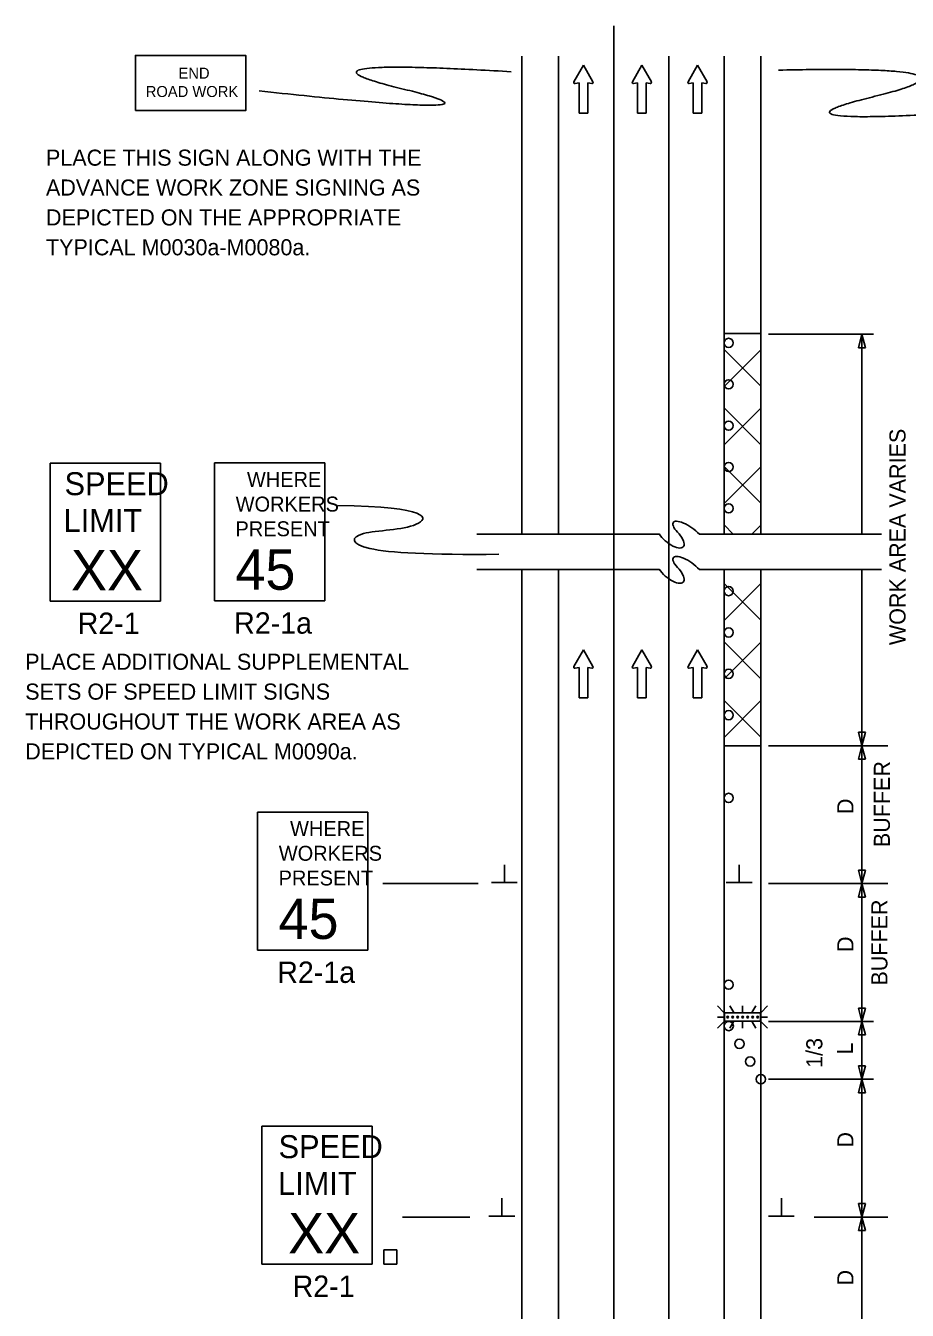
# Model space of a CAD drawing. Extents: x 16730 to 18471, y 7027 to 8225.
# Drawn here: x 16730 to 17113, y 7666 to 8225 of the extents above; entities that cross this region are included whole.
import ezdxf

# ---------------------------------------------------------------- set-up
doc = ezdxf.new("R2010")
doc.units = 0
for name, color, linetype in [('ALI_LEGAL_EX', 7, 'Continuous'), ('MT_SCRATCH_LEVEL_A', 7, 'Continuous'), ('MT_SCRATCH_LEVEL_E', 7, 'Continuous'), ('PAVT_EDGE_EX', 7, 'Continuous'), ('TRAFFIC_SIGNS_PR', 7, 'Continuous'), ('TYPICAL_EX', 7, 'Continuous'), ('TYPICAL_TEXT_DIMEN_PR', 7, 'Continuous')]:
    doc.layers.add(name, color=color, linetype=linetype)

msp = doc.modelspace()

# ---------------------------------------------------------------- linework, layer by layer
at = {"layer": 'ALI_LEGAL_EX'}
for points in [[(16985.65, 8225.29), (16985.65, 8200.29)], [(16985.65, 8216), (16985.65, 8191)], [(16985.65, 8211.96), (16985.65, 8200.29)], [(17009.65, 8211.96), (17009.65, 8200.29)], [(16985.65, 8125.29), (16985.65, 8100.29)], [(16985.65, 8125.29), (16985.65, 8100.29)], [(17009.65, 8125.29), (17009.65, 8100.29)], [(16985.65, 8025.29), (16985.65, 8004.01)], [(17009.65, 8025.29), (17009.65, 8000.29)], [(16985.65, 7961.57), (16985.65, 7936.57)], [(16985.65, 7925.29), (16985.65, 7900.29)], [(17009.65, 7925.29), (17009.65, 7900.29)], [(16985.65, 7825.29), (16985.65, 7800.29)], [(17009.65, 7825.29), (17009.65, 7800.29)], [(16985.65, 7725.29), (16985.65, 7700.29)], [(17009.65, 7725.29), (17009.65, 7700.29)]]:
    msp.add_lwpolyline(points, dxfattribs=at)
at = {"layer": 'MT_SCRATCH_LEVEL_A'}
for p, q in [((17049.65, 8068.41), (17033.65, 8084.41)), ((17033.65, 8068.3), (17049.65, 8084.3)), ((17049.65, 8042.96), (17033.65, 8058.96)), ((17033.65, 8042.85), (17049.65, 8058.85)), ((17049.65, 8017.5), (17033.65, 8033.5)), ((17033.65, 8017.39), (17049.65, 8033.39)), ((17037.68, 8004.02), (17033.65, 8008.05)), ((17045.64, 8003.92), (17049.65, 8007.94)), ((17049.65, 7966.59), (17033.65, 7982.59)), ((17033.65, 7966.48), (17049.65, 7982.48)), ((17049.65, 7941.13), (17033.65, 7957.13)), ((17033.65, 7941.02), (17049.65, 7957.02)), ((17049.65, 7915.68), (17033.65, 7931.68)), ((17033.65, 7915.57), (17049.65, 7931.57))]:
    msp.add_line(p, q, dxfattribs=at)
at = {"layer": 'MT_SCRATCH_LEVEL_E'}
for p, q in [((16972.46, 8208.07), (16968.34, 8200.83)), ((16972.46, 8208.07), (16968.34, 8200.83)), ((16976.6, 8200.83), (16972.46, 8208.07)), ((16976.6, 8200.83), (16972.46, 8208.07)), ((16997.88, 8208.07), (16993.77, 8200.83)), ((16997.88, 8208.07), (16993.77, 8200.83)), ((17002.03, 8200.83), (16997.88, 8208.07)), ((17002.03, 8200.83), (16997.88, 8208.07)), ((17022.09, 8208.07), (17017.98, 8200.83)), ((17022.09, 8208.07), (17017.98, 8200.83)), ((17026.24, 8200.83), (17022.09, 8208.07)), ((17026.24, 8200.83), (17022.09, 8208.07)), ((16968.83, 8200.14), (16970.6, 8200.46)), ((16968.83, 8200.14), (16970.6, 8200.46)), ((16970.6, 8200.46), (16970.6, 8187.2)), ((16970.6, 8200.46), (16970.6, 8187.2)), ((16974.35, 8187.2), (16974.35, 8200.46)), ((16974.35, 8200.46), (16976.12, 8200.14)), ((16974.35, 8187.2), (16974.35, 8200.46)), ((16974.35, 8200.46), (16976.12, 8200.14)), ((16994.25, 8200.14), (16996.03, 8200.46)), ((16994.25, 8200.14), (16996.03, 8200.46)), ((16996.03, 8200.46), (16996.03, 8187.2)), ((16996.03, 8200.46), (16996.03, 8187.2)), ((16999.77, 8187.2), (16999.77, 8200.46)), ((16999.77, 8200.46), (17001.55, 8200.14)), ((16999.77, 8187.2), (16999.77, 8200.46)), ((16999.77, 8200.46), (17001.55, 8200.14)), ((17018.47, 8200.14), (17020.24, 8200.46)), ((17018.47, 8200.14), (17020.24, 8200.46)), ((17020.24, 8200.46), (17020.24, 8187.2)), ((17020.24, 8200.46), (17020.24, 8187.2)), ((17023.98, 8187.2), (17023.98, 8200.46)), ((17023.98, 8200.46), (17025.76, 8200.14)), ((17023.98, 8187.2), (17023.98, 8200.46)), ((17023.98, 8200.46), (17025.76, 8200.14)), ((16970.6, 8187.2), (16974.35, 8187.2)), ((16970.6, 8187.2), (16974.35, 8187.2)), ((16996.03, 8187.2), (16999.77, 8187.2)), ((16996.03, 8187.2), (16999.77, 8187.2)), ((17020.24, 8187.2), (17023.98, 8187.2)), ((17020.24, 8187.2), (17023.98, 8187.2)), ((16972.46, 7953.64), (16968.34, 7946.4)), ((16972.46, 7953.64), (16968.34, 7946.4)), ((16976.6, 7946.4), (16972.46, 7953.64)), ((16976.6, 7946.4), (16972.46, 7953.64)), ((16997.88, 7953.64), (16993.77, 7946.4)), ((16997.88, 7953.64), (16993.77, 7946.4)), ((17002.03, 7946.4), (16997.88, 7953.64)), ((17002.03, 7946.4), (16997.88, 7953.64)), ((17022.09, 7953.64), (17017.98, 7946.4)), ((17022.09, 7953.64), (17017.98, 7946.4)), ((17026.24, 7946.4), (17022.09, 7953.64)), ((17026.24, 7946.4), (17022.09, 7953.64)), ((16968.83, 7945.72), (16970.6, 7946.03)), ((16968.83, 7945.72), (16970.6, 7946.03)), ((16970.6, 7946.03), (16970.6, 7932.78)), ((16970.6, 7946.03), (16970.6, 7932.78)), ((16974.35, 7932.78), (16974.35, 7946.03)), ((16974.35, 7946.03), (16976.12, 7945.72)), ((16974.35, 7932.78), (16974.35, 7946.03)), ((16974.35, 7946.03), (16976.12, 7945.72)), ((16994.25, 7945.72), (16996.03, 7946.03)), ((16994.25, 7945.72), (16996.03, 7946.03)), ((16996.03, 7946.03), (16996.03, 7932.78)), ((16996.03, 7946.03), (16996.03, 7932.78)), ((16999.77, 7932.78), (16999.77, 7946.03)), ((16999.77, 7946.03), (17001.55, 7945.72)), ((16999.77, 7932.78), (16999.77, 7946.03)), ((16999.77, 7946.03), (17001.55, 7945.72)), ((17018.47, 7945.72), (17020.24, 7946.03)), ((17018.47, 7945.72), (17020.24, 7946.03)), ((17020.24, 7946.03), (17020.24, 7932.78)), ((17020.24, 7946.03), (17020.24, 7932.78)), ((17023.98, 7932.78), (17023.98, 7946.03)), ((17023.98, 7946.03), (17025.76, 7945.72)), ((17023.98, 7932.78), (17023.98, 7946.03)), ((17023.98, 7946.03), (17025.76, 7945.72)), ((16970.6, 7932.78), (16974.35, 7932.78)), ((16970.6, 7932.78), (16974.35, 7932.78)), ((16996.03, 7932.78), (16999.77, 7932.78)), ((16996.03, 7932.78), (16999.77, 7932.78)), ((17020.24, 7932.78), (17023.98, 7932.78)), ((17020.24, 7932.78), (17023.98, 7932.78))]:
    msp.add_line(p, q, dxfattribs=at)
for centre, start, end in [((16968.75, 8200.6), 150.4248, 279.9638), ((16968.75, 8200.6), 150.4248, 279.9638), ((16976.19, 8200.6), 260.0362, 29.7731), ((16976.19, 8200.6), 260.0362, 29.7731), ((16994.18, 8200.6), 150.4248, 279.9638), ((16994.18, 8200.6), 150.4248, 279.9638), ((17001.62, 8200.6), 260.0362, 29.7731), ((17001.62, 8200.6), 260.0362, 29.7731), ((17018.39, 8200.6), 150.4248, 279.9638), ((17018.39, 8200.6), 150.4248, 279.9638), ((17025.83, 8200.6), 260.0362, 29.7731), ((17025.83, 8200.6), 260.0362, 29.7731), ((16968.75, 7946.18), 150.4248, 279.9638), ((16968.75, 7946.18), 150.4248, 279.9638), ((16976.19, 7946.18), 260.0362, 29.7731), ((16976.19, 7946.18), 260.0362, 29.7731), ((16994.18, 7946.18), 150.4248, 279.9638), ((16994.18, 7946.18), 150.4248, 279.9638), ((17001.62, 7946.18), 260.0362, 29.7731), ((17001.62, 7946.18), 260.0362, 29.7731), ((17018.39, 7946.18), 150.4248, 279.9638), ((17018.39, 7946.18), 150.4248, 279.9638), ((17025.83, 7946.18), 260.0362, 29.7731), ((17025.83, 7946.18), 260.0362, 29.7731)]:
    msp.add_arc(centre, 0.463, start, end, dxfattribs=at)
at = {"layer": 'PAVT_EDGE_EX'}
for p, q in [((16945.65, 8211.96), (16945.65, 8004.01)), ((16961.65, 8211.96), (16961.65, 8004.01)), ((16985.65, 8211.96), (16985.65, 7344.79)), ((17009.65, 8211.96), (17009.65, 7344.79)), ((17033.65, 8211.96), (17033.65, 8004.01)), ((17049.65, 8211.96), (17049.65, 8004.01)), ((16985.65, 8097.28), (16985.65, 7344.79)), ((17009.65, 8097.28), (17009.65, 7344.79)), ((17033.65, 8091.4), (17049.65, 8091.4)), ((17035.65, 8015.25), (17035.65, 8015.25)), ((16945.65, 7988.69), (16945.65, 7942.5)), ((16961.65, 7988.69), (16961.65, 7942.41)), ((17033.65, 7988.69), (17033.65, 7942.16)), ((17049.65, 7988.69), (17049.65, 7942.41)), ((16945.65, 7942.5), (16945.65, 7379.34)), ((16961.65, 7942.41), (16961.65, 7379.34)), ((17033.65, 7942.16), (17033.65, 7379.34)), ((17049.65, 7942.41), (17049.65, 7379.34)), ((17033.65, 7911.96), (17049.65, 7911.96))]:
    msp.add_line(p, q, dxfattribs=at)
msp.add_lwpolyline([(17049.65, 7795.68), (17049.65, 7911.96), (17033.65, 7911.96), (17033.65, 7795.68)], close=True, dxfattribs=at)
at = {"layer": 'TRAFFIC_SIGNS_PR'}
for p, q in [((16740.5, 8034.9), (16788.5, 8034.9)), ((16740.5, 7974.9), (16740.5, 8034.9)), ((16788.5, 7974.9), (16788.5, 8034.9)), ((16812, 8035.01), (16860, 8035.01)), ((16812, 7975.01), (16812, 8035.01)), ((16860, 7975.01), (16860, 8035.01)), ((16740.5, 7974.9), (16788.5, 7974.9)), ((16812, 7975.01), (16860, 7975.01)), ((16830.76, 7883.05), (16878.76, 7883.05)), ((16830.76, 7823.05), (16830.76, 7883.05)), ((16878.76, 7823.05), (16878.76, 7883.05)), ((16830.76, 7823.05), (16878.76, 7823.05)), ((17030.76, 7798.72), (17033.58, 7795.9)), ((17037.85, 7795.9), (17036.22, 7798.72)), ((17041.67, 7795.9), (17041.67, 7798.72)), ((17045.8, 7795.9), (17047.43, 7798.72)), ((17049.75, 7795.9), (17052.57, 7798.72)), ((17033.58, 7793.87), (17030.76, 7793.87)), ((17035.22, 7793.87), (17035.22, 7793.87)), ((17037.4, 7793.87), (17037.4, 7793.87)), ((17039.57, 7793.87), (17039.57, 7793.87)), ((17041.74, 7793.87), (17041.74, 7793.87)), ((17043.92, 7793.87), (17043.92, 7793.87)), ((17046.09, 7793.87), (17046.09, 7793.87)), ((17048.26, 7793.87), (17048.26, 7793.87)), ((17049.75, 7793.87), (17052.57, 7793.87)), ((17030.76, 7789.02), (17033.58, 7791.83)), ((17036.2, 7789.01), (17037.83, 7791.83)), ((17041.67, 7791.83), (17041.67, 7789.01)), ((17047.46, 7789.01), (17045.83, 7791.83)), ((17049.75, 7791.83), (17052.57, 7789.01)), ((16832.67, 7746.41), (16880.67, 7746.41)), ((16832.67, 7686.41), (16832.67, 7746.41)), ((16880.67, 7686.41), (16880.67, 7746.41)), ((16832.67, 7686.41), (16880.67, 7686.41))]:
    msp.add_line(p, q, dxfattribs=at)
for points in [[(16777.61, 8188.32), (16825.61, 8188.32), (16825.61, 8212.32), (16777.61, 8212.32)], [(17049.52, 7792.07), (17033.81, 7792.07), (17033.81, 7795.67), (17049.52, 7795.67)], [(16885.68, 7686.41), (16891.28, 7686.41), (16891.28, 7692.58), (16885.68, 7692.58)]]:
    msp.add_lwpolyline(points, close=True, dxfattribs=at)
for centre, radius in [((17035.65, 8087.25), 2), ((17035.65, 8069.25), 2), ((17035.65, 8051.25), 2), ((17035.65, 8033.25), 2), ((17035.65, 8015.25), 2), ((17035.65, 7979.25), 2), ((17035.65, 7961.25), 2), ((17035.65, 7943.25), 2), ((17035.65, 7925.25), 2), ((17035.65, 7889.25), 2), ((17035.65, 7807.96), 2), ((17035.24, 7793.87), 0.379), ((17037.39, 7793.87), 0.379), ((17039.57, 7793.87), 0.379), ((17041.74, 7793.87), 0.379), ((17043.91, 7793.87), 0.379), ((17046.09, 7793.87), 0.379), ((17048.26, 7793.87), 0.379), ((17035.7, 7789.96), 2), ((17040.35, 7782.25), 2), ((17044.99, 7774.54), 2), ((17049.65, 7766.83), 2)]:
    msp.add_circle(centre, radius, dxfattribs=at)
for points in [[(16831.42, 8196.9), (16950.78, 8184.01), (16836.87, 8211.59), (16941.12, 8205.24)], [(17156.66, 8188.77), (17041.44, 8180.53), (17155.34, 8208.11), (17057.4, 8205.95)]]:
    msp.add_open_spline(points, degree=2, dxfattribs=at)
at = {"layer": 'TYPICAL_EX'}
for p, q in [((16926.17, 8004.01), (17005.48, 8004.01)), ((17022.9, 8004.01), (17102.17, 8004.01)), ((16926.17, 7988.69), (17005.48, 7988.69)), ((17022.9, 7988.69), (17102.17, 7988.69))]:
    msp.add_line(p, q, dxfattribs=at)
for centre, major_axis, ratio, start_param, end_param in [((17018.27, 8004.28), (6.66, -4.85), 0.346236, 1.077134, 4.299707), ((17010.23, 8003.47), (-5.67, 4.94), 0.423114, 0.994299, 4.377734), ((17018.27, 7988.96), (6.66, -4.85), 0.346236, 1.077134, 4.299707), ((17010.23, 7988.15), (-5.67, 4.94), 0.423114, 0.994299, 4.377734)]:
    msp.add_ellipse(centre, major_axis=major_axis, ratio=ratio, start_param=start_param, end_param=end_param, dxfattribs=at)
at = {"layer": 'TYPICAL_TEXT_DIMEN_PR'}
for p, q in [((17052.95, 8091), (17098.65, 8091)), ((17092.08, 8085.14), (17093.65, 8091)), ((17093.65, 8091), (17095.22, 8085.14)), ((17093.65, 8091), (17093.65, 8003.81)), ((17093.65, 8085.14), (17092.08, 8085.14)), ((17095.22, 8085.14), (17093.65, 8085.14)), ((17093.65, 7988.65), (17093.65, 7911.96)), ((17093.65, 7911.96), (17092.08, 7917.82)), ((17092.08, 7917.82), (17093.65, 7917.82)), ((17093.65, 7917.82), (17095.22, 7917.82)), ((17095.22, 7917.82), (17093.65, 7911.96)), ((17052.98, 7911.96), (17104.89, 7911.96)), ((17092.08, 7906.1), (17093.65, 7911.96)), ((17093.65, 7911.96), (17093.65, 7851.96)), ((17093.65, 7911.96), (17095.22, 7906.1)), ((17093.65, 7906.1), (17092.08, 7906.1)), ((17095.22, 7906.1), (17093.65, 7906.1)), ((16938.09, 7852.39), (16938.09, 7860.17)), ((17040.18, 7852.39), (17040.18, 7860.17)), ((17093.65, 7851.96), (17092.08, 7857.82)), ((17092.08, 7857.82), (17093.65, 7857.82)), ((17093.65, 7857.82), (17095.22, 7857.82)), ((17095.22, 7857.82), (17093.65, 7851.96)), ((16885.24, 7851.96), (16926.72, 7851.96)), ((16943.72, 7852.39), (16932.47, 7852.39)), ((17045.81, 7852.39), (17034.56, 7852.39)), ((17052.98, 7851.96), (17104.89, 7851.96)), ((17092.08, 7846.1), (17093.65, 7851.96)), ((17093.65, 7851.96), (17093.65, 7791.96)), ((17093.65, 7851.96), (17095.22, 7846.1)), ((17093.65, 7846.1), (17092.08, 7846.1)), ((17095.22, 7846.1), (17093.65, 7846.1)), ((17093.65, 7791.96), (17092.08, 7797.82)), ((17092.08, 7797.82), (17093.65, 7797.82)), ((17093.65, 7797.82), (17095.22, 7797.82)), ((17095.22, 7797.82), (17093.65, 7791.96)), ((17052.95, 7791.96), (17098.65, 7791.96)), ((17092.08, 7786.1), (17093.65, 7791.96)), ((17093.65, 7791.96), (17093.65, 7766.83)), ((17093.65, 7791.96), (17095.22, 7786.1)), ((17093.65, 7786.1), (17092.08, 7786.1)), ((17095.22, 7786.1), (17093.65, 7786.1)), ((17093.65, 7766.83), (17092.08, 7772.7)), ((17092.08, 7772.7), (17093.65, 7772.7)), ((17093.65, 7772.7), (17095.22, 7772.7)), ((17095.22, 7772.7), (17093.65, 7766.83)), ((17052.95, 7766.83), (17098.65, 7766.83)), ((17092.08, 7760.97), (17093.65, 7766.83)), ((17093.65, 7766.83), (17093.65, 7706.83)), ((17093.65, 7766.83), (17095.22, 7760.97)), ((17093.65, 7760.97), (17092.08, 7760.97)), ((17095.22, 7760.97), (17093.65, 7760.97)), ((16937.02, 7707.26), (16937.02, 7715.05)), ((17058.58, 7707.26), (17058.58, 7715.05)), ((17093.65, 7706.83), (17092.08, 7712.7)), ((17092.08, 7712.7), (17093.65, 7712.7)), ((17093.65, 7712.7), (17095.22, 7712.7)), ((17095.22, 7712.7), (17093.65, 7706.83)), ((16893.76, 7706.83), (16923.12, 7706.83)), ((16942.65, 7707.26), (16931.4, 7707.26)), ((17064.21, 7707.26), (17052.96, 7707.26)), ((17072.81, 7706.83), (17104.89, 7706.83)), ((17092.08, 7700.97), (17093.65, 7706.83)), ((17093.65, 7706.83), (17093.65, 7646.83)), ((17093.65, 7706.83), (17095.22, 7700.97)), ((17093.65, 7700.97), (17092.08, 7700.97)), ((17095.22, 7700.97), (17093.65, 7700.97))]:
    msp.add_line(p, q, dxfattribs=at)
msp.add_open_spline([(16865.72, 8016.47), (16905.99, 8015.89), (16905.32, 8005.77), (16871.09, 8005.77), (16871.09, 7996.72), (16905.3, 7994.96), (16935.75, 7995.26)], degree=3, dxfattribs=at)

# ---------------------------------------------------------------- texts
at = {"layer": 'TRAFFIC_SIGNS_PR'}
for s, height, p in [('END', 4.789, (16796.36, 8202.23)), ('ROAD WORK', 4.789, (16782.12, 8194.25)), ('PLACE THIS SIGN ALONG WITH THE', 7, (16738.72, 8164.36)), ('ADVANCE WORK ZONE SIGNING AS', 7, (16738.72, 8151.36)), ('DEPICTED ON THE APPROPRIATE', 7, (16738.72, 8138.36)), ('TYPICAL M0030a-M0080a.', 7, (16738.72, 8125.36)), ('SPEED', 10, (16746.79, 8020.98)), ('WHERE', 6.5, (16826.13, 8024.61)), ('WORKERS', 6.5, (16821.23, 8013.86)), ('LIMIT', 10, (16746.38, 8004.98)), ('PRESENT', 6.5, (16821.14, 8003.11)), ('XX', 17.538, (16749.63, 7979.6)), ('45', 17.538, (16821.13, 7979.83)), ('R2-1', 9.3, (16752.51, 7960.6)), ('R2-1a', 9.3, (16820.56, 7960.71)), ('PLACE ADDITIONAL SUPPLEMENTAL', 7, (16729.69, 7945)), ('SETS OF SPEED LIMIT SIGNS', 7, (16729.69, 7932)), ('THROUGHOUT THE WORK AREA AS', 7, (16729.69, 7919)), ('DEPICTED ON TYPICAL M0090a.', 7, (16729.69, 7906)), ('WHERE', 6.5, (16844.89, 7872.65)), ('WORKERS', 6.5, (16839.99, 7861.9)), ('PRESENT', 6.5, (16839.9, 7851.15)), ('45', 17.538, (16839.89, 7827.87)), ('R2-1a', 9.3, (16839.32, 7808.75)), ('SPEED', 10, (16839.88, 7732.49)), ('LIMIT', 10, (16839.67, 7716.49)), ('XX', 17.538, (16844.06, 7691.11)), ('R2-1', 9.3, (16846.01, 7672.11))]:
    msp.add_text(s, height=height, dxfattribs=at).set_placement(p)
at = {"layer": 'TYPICAL_TEXT_DIMEN_PR'}
for s, p in [('WORK AREA VARIES', (17112.58, 7955.74)), ('BUFFER', (17105.79, 7867.84)), ('D', (17089.92, 7882.2)), ('BUFFER', (17104.71, 7807.6)), ('D', (17089.92, 7822.2)), ('1/3', (17076.41, 7771.78)), ('L', (17089.71, 7777.57)), ('D', (17089.92, 7737.08)), ('D', (17089.92, 7677.08))]:
    msp.add_text(s, height=7, rotation=90, dxfattribs=at).set_placement(p)

doc.saveas('drawing.dxf')
